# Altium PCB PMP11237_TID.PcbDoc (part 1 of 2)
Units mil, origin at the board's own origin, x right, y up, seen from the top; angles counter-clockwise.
Board outline 9200 x 5000 mil, 2 copper layers (Top Layer, Bottom Layer), stack 62 mil thick; 181 components, 96 nets, 449 pads, 4 vias.
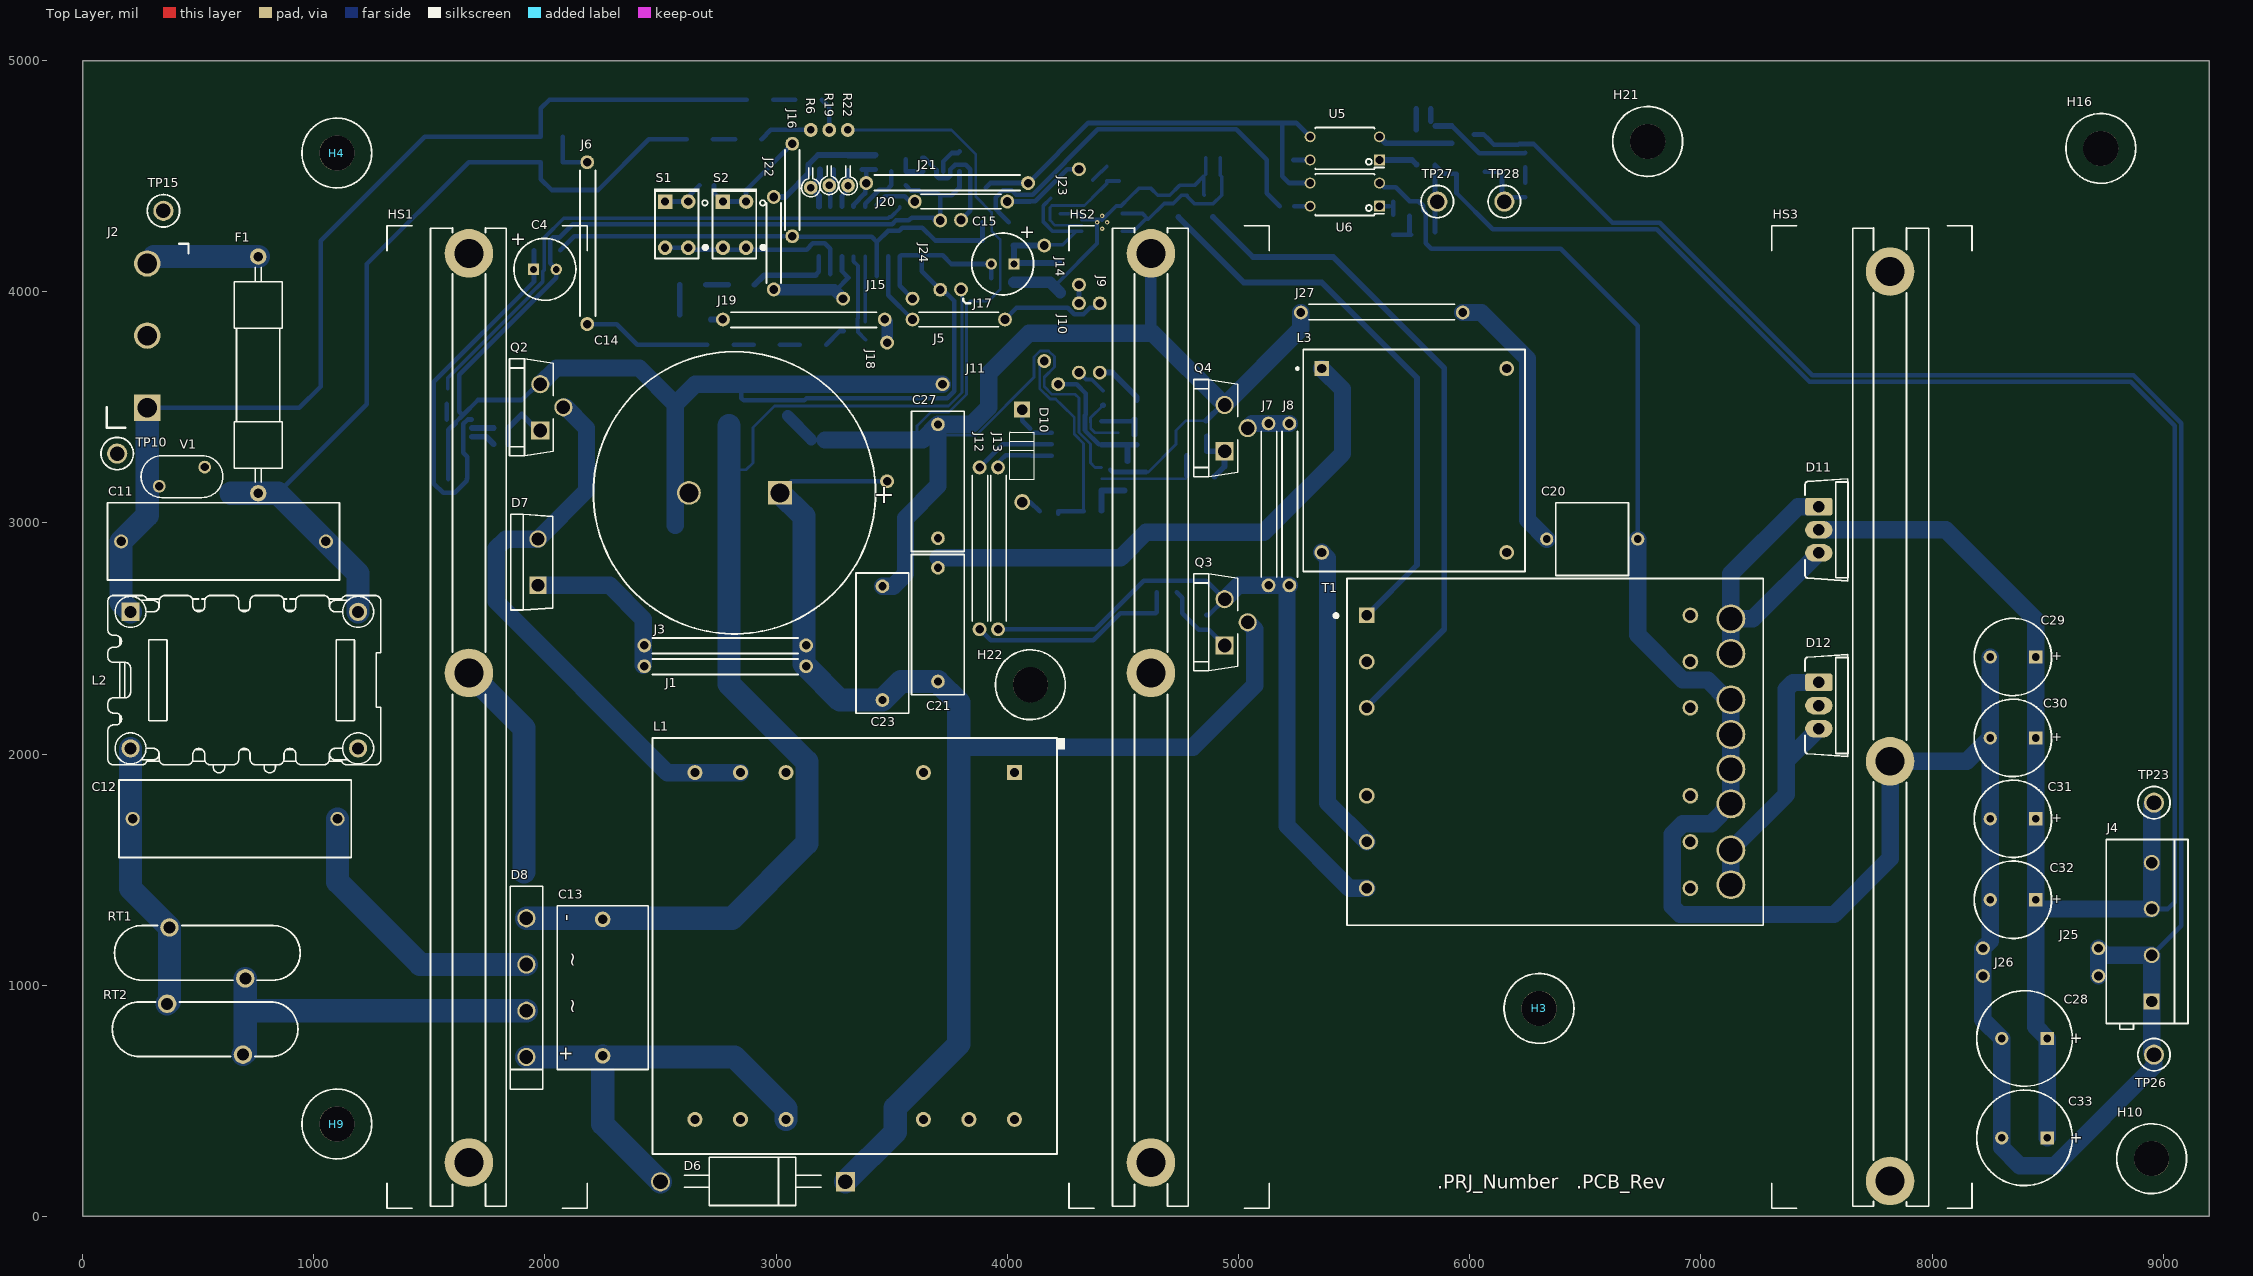
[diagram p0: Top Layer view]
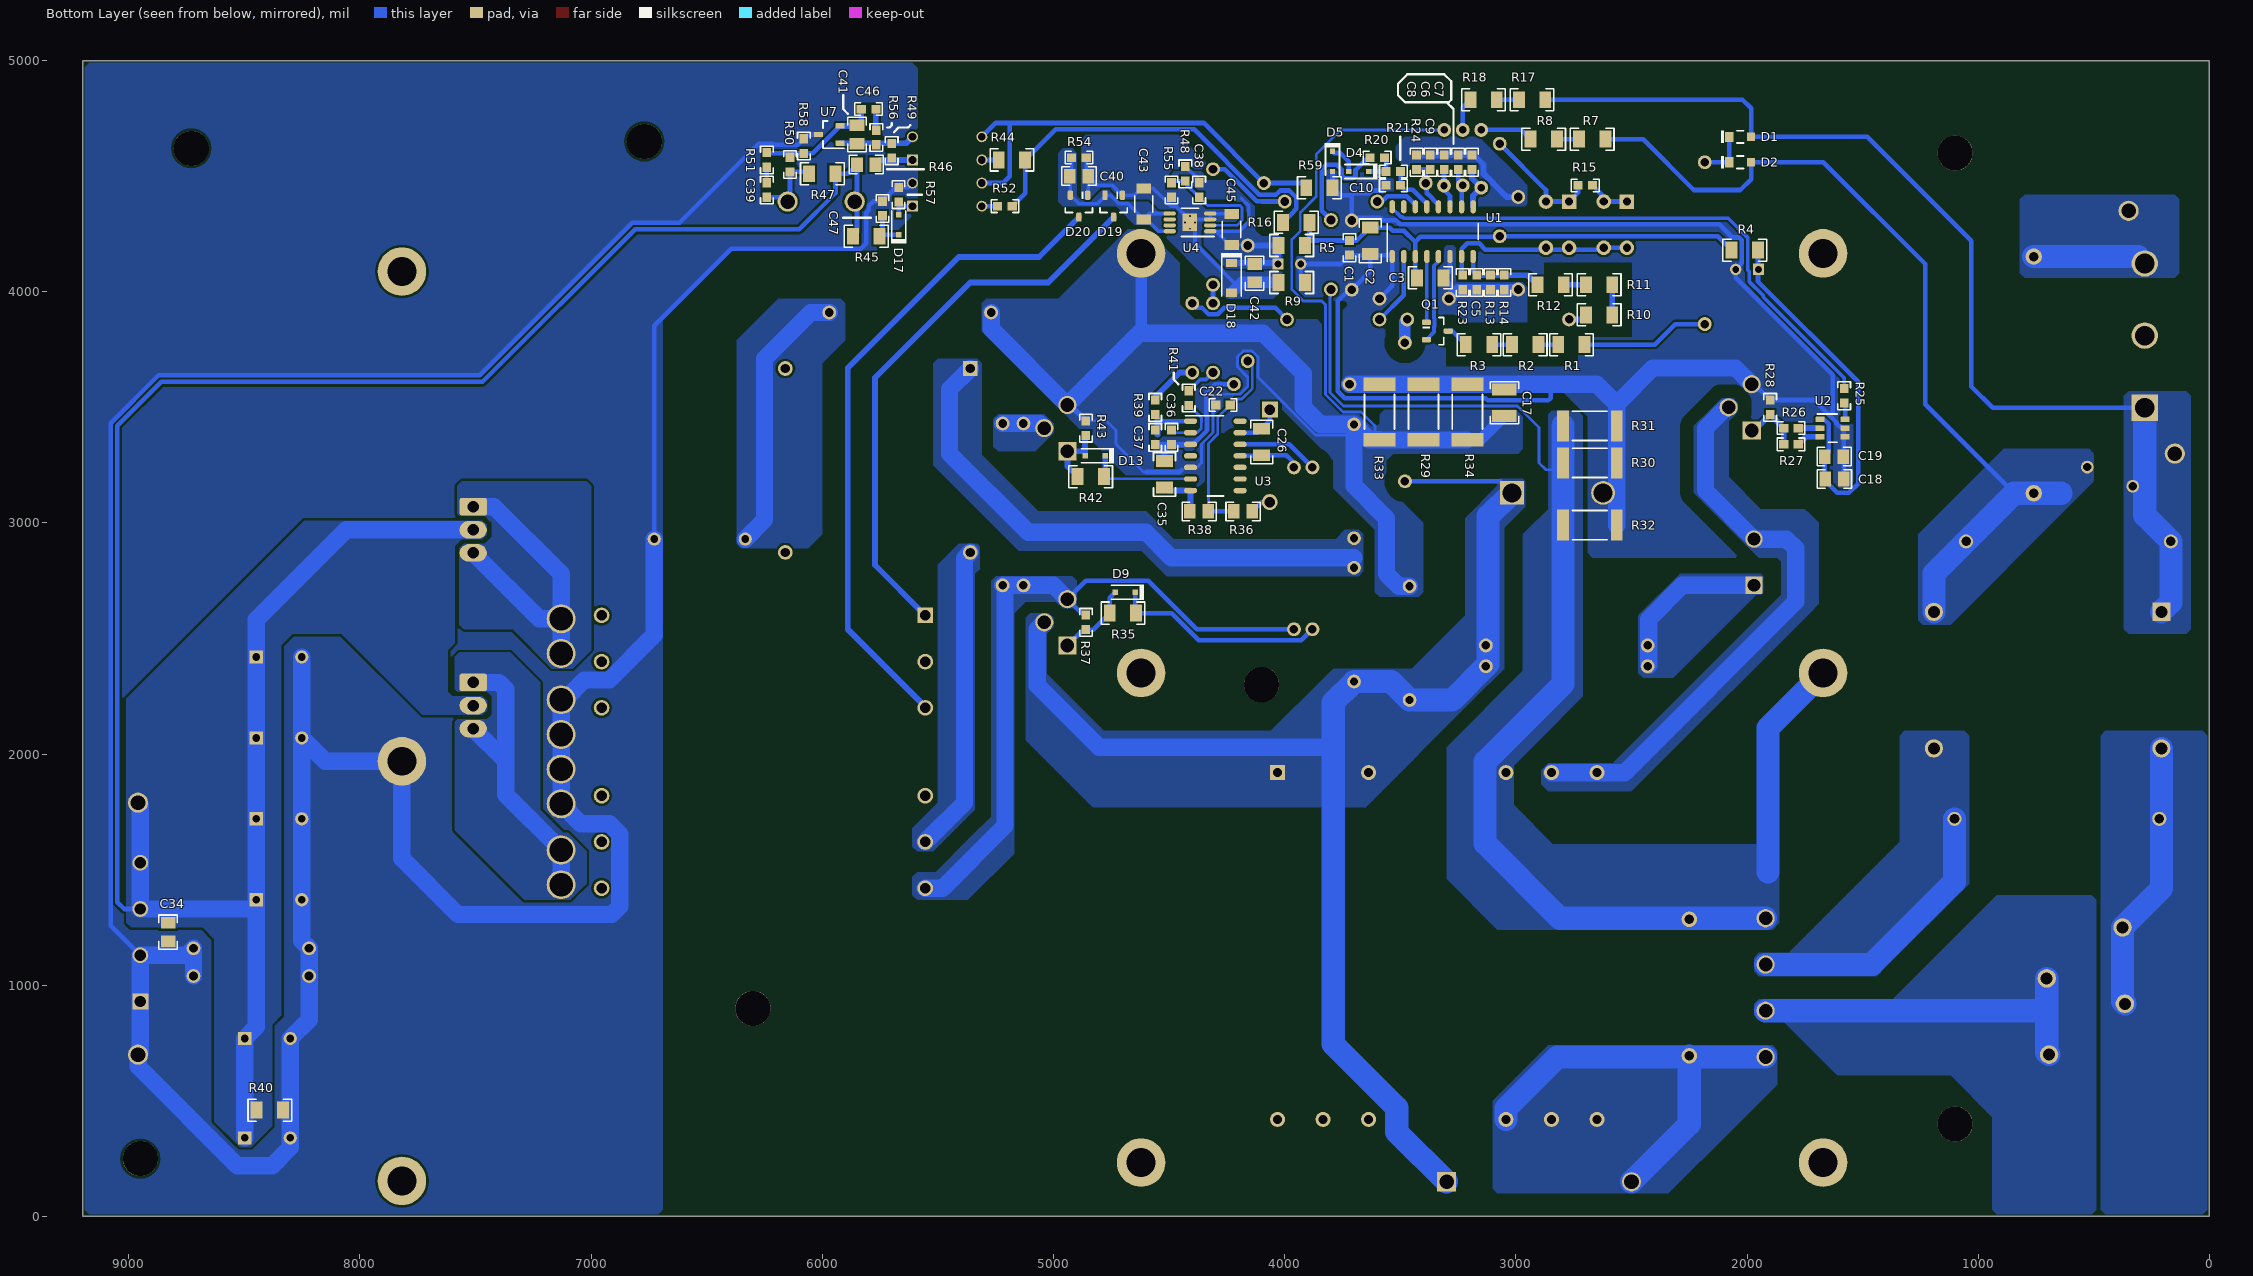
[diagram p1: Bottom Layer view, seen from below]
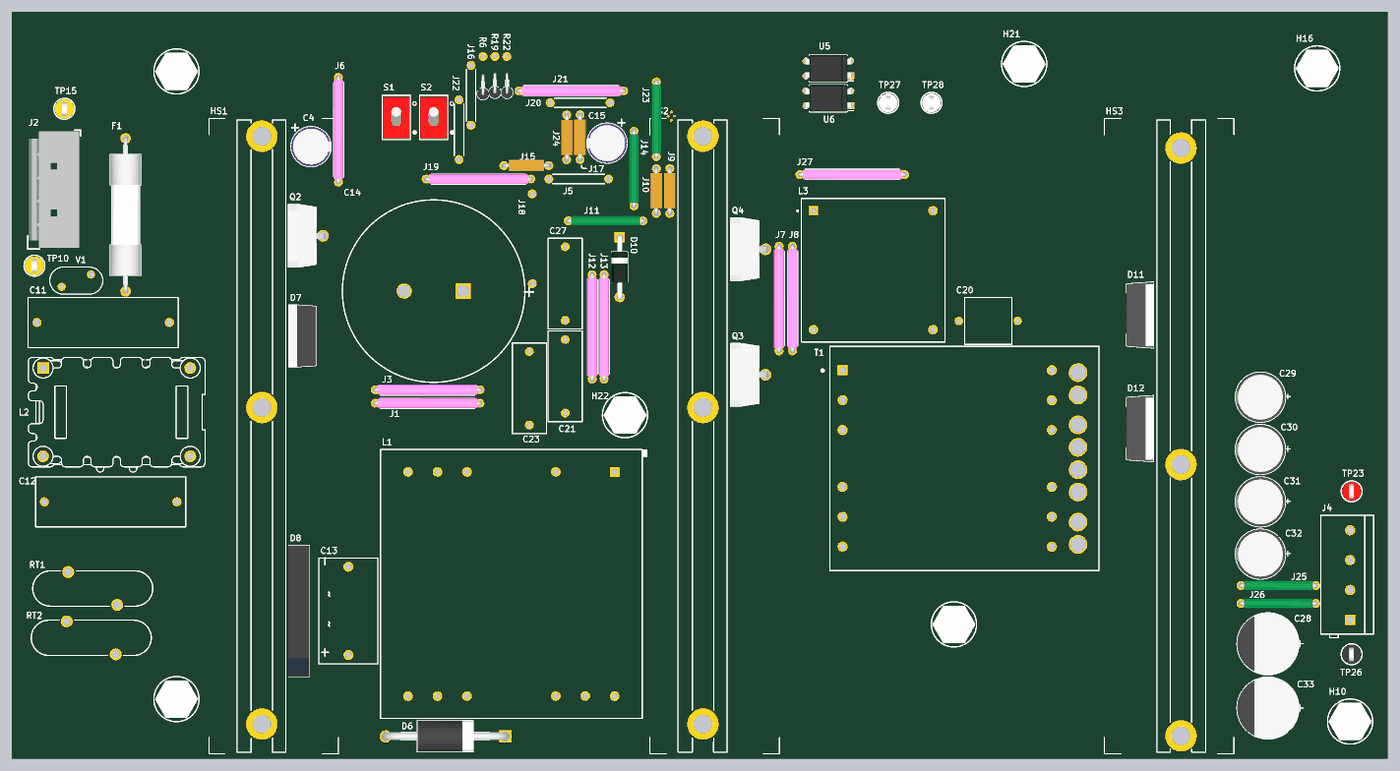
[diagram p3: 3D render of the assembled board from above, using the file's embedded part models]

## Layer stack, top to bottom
Top Solder: solder mask 0.4, Solder Resist, Dk 3.5
Top Layer: signal copper 1.4
Dielectric1: core 59.2, FR-4, Dk 4.8
Bottom Layer: signal copper 1.4
Bottom Solder: solder mask 0.4, Solder Resist, Dk 3.5

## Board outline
0,0 9200,0 9200,5000 0,5000

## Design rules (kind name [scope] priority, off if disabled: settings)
AcuteAngle [All] p1: minimum=4.50000000000000E+0001 checktracksonly=FALSE
AssemblyTestPointUsage [All] p1: valid=2
Clearance Clearance_1 [InNetClass('HV') vs (InNet('AGND') OR InNet('PGND') OR InNet('SEC_0V') OR InNet('PFCCS') OR InNet('LLC_RCS'))] p1: gap=60
Clearance Clearance_Keepouts [((IsTrack Or IsArc) And Not InPoly) And IsFree and IsKeepOut vs ((IsTrack Or IsArc) And Not InPoly) And IsFree and IsKeepOut] p2: gap=0
Clearance Clearance_BoardEdge_MountingHoles [OnCopper and InComponentClass('Mounting Holes') vs IsKeepOut] p3: gap=40
Clearance Clearance_BoardEdge_Poly [OnCopper and InPoly vs IsKeepOut] p4: gap=25
Clearance Clearance_BoardEdge [OnCopper and Not InComponentClass('Logo') and not InComponentClass('FiducialMark') and not InRegion(1000,500,4000,800) and Not IsKeepout vs IsKeepOut] p5: gap=75
Clearance Clearance_Poly [InPolygon] p6: gap=10
Clearance [All] p7: gap=7.87
ComponentClearance ComponentClearance_MountingHoles_FiducialMarks [InComponentClass('Mounting Holes') vs InComponentClass('FiducialMark')] p1: gap=20 collisioncheckmode=3 verticalgap=10 showdistances=FALSE
ComponentClearance ComponentClearance_Shunt [InComponentClass('Header') vs InComponentClass('Shunt')] p2: gap=0 collisioncheckmode=3 verticalgap=0 showdistances=FALSE
ComponentClearance ComponentClearance_Logo [InComponentClass('Logo')] p3: gap=5 collisioncheckmode=3 verticalgap=10 showdistances=FALSE
ComponentClearance ComponentClearance_ScrewToNut [(HasFootprint('NY PMS 440 0025 PH')) vs (HasFootprint('Keystone_1902C'))] p4: gap=20 collisioncheckmode=3 verticalgap=100000 showdistances=FALSE
ComponentClearance ComponentClearance_MountingHoles [InComponentClass('Mounting Holes')] p5: gap=20 collisioncheckmode=3 verticalgap=10 showdistances=FALSE
ComponentClearance ComponentClearance_SmallPassives [HasFootprint('0201*') or HasFootprint('0402*') or HasFootprint('0508') or HasFootprint('0603*') or HasFootprint('0612') or HasFootprint('0805*') or HasFootprint('0815*') or HasFootprint('0830*') or HasFootprint('1206*') or HasFootprint('1210*') or HasFootprint('1808*') or HasFootprint('1812*') or HasFootprint('1825*') or HasFootprint('2010*') or HasFootprint('2220*') or HasFootprint('2225*') or HasFootprint('2512*') or HasFootprint('2728*') or HasFootprint('3518*') vs HasFootprint('0201*') or HasFootprint('0402*') or HasFootprint('0508') or HasFootprint('0603*') or HasFootprint('0612') or HasFootprint('0805*') or HasFootprint('0815*') or HasFootprint('0830*') or HasFootprint('1206*') or HasFootprint('1210*') or HasFootprint('1808*') or HasFootprint('1812*') or HasFootprint('1825*') or HasFootprint('2010*') or HasFootprint('2220*') or HasFootprint('2225*') or HasFootprint('2512*') or HasFootprint('2728*') or HasFootprint('3518*')] p6: gap=20 collisioncheckmode=3 verticalgap=20 showdistances=FALSE
ComponentClearance ComponentClearance_THtoSMT [IsThruComponent vs IsSMTComponent] p7: gap=10 collisioncheckmode=3 verticalgap=10 showdistances=FALSE
ComponentClearance ComponentClearance_THtoTH [IsThruComponent vs IsThruComponent] p8: gap=6 collisioncheckmode=3 verticalgap=6 showdistances=FALSE
ComponentClearance [All] p9: gap=10 collisioncheckmode=3 verticalgap=10 showdistances=FALSE
DiffPairsRouting [All] p1: maxlimit=100 minlimit=10 mostfreqgap=10 toplayer_minwidth=15 toplayer_maxwidth=15 toplayer_prefwidth=15 bottomlayer_minwidth=15 bottomlayer_maxwidth=15 bottomlayer_prefwidth=15 maxuncoupledlength=1000
FabricationTestPointUsage TestPointUsage [All] p1: valid=2 allowmultiple=FALSE
FabricationTestpoint Testpoint [All] p1: side=3 testpointundercomponent=TRUE minsize=40 maxsize=100 preferedsize=60 minholesize=0 maxholesize=40 preferedholesize=32 testpointgrid=1 allowsidetop=TRUE allowsidebottom=TRUE usegrid=TRUE gridtolerance=0.01
FanoutControl Fanout_LCC [IsLCC] p1: bgadir=Out bgaviamode=Centered fanoutstyle=Auto fanoutdirection=Alternating viagrid=1 // Fanout_LCC (Default Rule)
FanoutControl Fanout_BGA [IsBGA] p2: bgadir=Out bgaviamode=Centered fanoutstyle=Auto fanoutdirection=Alternating viagrid=1 // Fanout_BGA (Default Rule)
FanoutControl Fanout_Default [All] p4: bgadir=Out bgaviamode=Centered fanoutstyle=Auto fanoutdirection=Alternating viagrid=1 // Fanout_Default (Default Rule)
FanoutControl Fanout_Small [(CompPinCount < 5)] p5: bgadir=Out bgaviamode=Centered fanoutstyle=Auto fanoutdirection=OutThenIn viagrid=1 // Fanout_Small (Default Rule)
Height [All] p1: minheight=0 maxheight=3000 prefheight=500
HoleSize [All] p1: absolutevalues=TRUE maxlimit=251 minlimit=7 maxpercent=80.000 minpercent=20.000
MinimumAnnularRing MinimumAnnularRing_ThermalPadVias [IsVia and InAnyComponent] p1: minimumring=5.91
MinimumAnnularRing [All] p2: minimumring=6
MinimumSolderMaskSliver MinimumSolderMaskSliver_Logo [InComponentClass('Logo') vs InComponentClass('Logo')] p1: minsoldermaskwidth=0.7
MinimumSolderMaskSliver [All] p2: minsoldermaskwidth=2
PlaneConnect [All] p1: planeconnectstyle=Relief reliefexpansion=10 reliefentries=4 reliefconductorwidth=10 reliefairgap=10
PolygonConnect PolygonConnect_13 [All vs IsNamedPolygon('C35_2') Or  IsNamedPolygon('L3_6') Or  IsNamedPolygon('PFCCS') Or  IsNamedPolygon('D7_2') Or  IsNamedPolygon('C40_2') Or  IsNamedPolygon('D7_1') Or  IsNamedPolygon('D11_1') Or  IsNamedPolygon('C12_1') Or  IsNamedPolygon('J7_2') Or  IsNamedPolygon('D8_2') Or  IsNamedPolygon('C20_2') Or  IsNamedPolygon('C12_2') Or  IsNamedPolygon('C15_1') Or  IsNamedPolygon('J7_1') Or  IsNamedPolygon('C13_1') Or  IsNamedPolygon('D12_1') Or  IsNamedPolygon('+Vout') Or  IsNamedPolygon('LLC_RCS') Or  IsNamedPolygon('AGND') Or  IsNamedPolygon('PGND') Or  IsNamedPolygon('AGND1') Or  IsNamedPolygon('SGND') Or  IsNamedPolygon('C21_2') Or  IsNamedPolygon('Bulk') Or  IsNamedPolygon('C40_1') Or  IsNamedPolygon('AC2') Or  IsNamedPolygon('AC1') Or  IsNamedPolygon('F1_2')] p1: connectstyle=Direct reliefconductorwidth=10 reliefentries=4 polygonreliefangle="90 Angle" airgapwidth=10
PolygonConnect PolygonConnect_12 [All vs IsNamedPolygon('F1_2') Or  IsNamedPolygon('+Vout') Or  IsNamedPolygon('AC1') Or  IsNamedPolygon('C40_2') Or  IsNamedPolygon('C12_2') Or  IsNamedPolygon('D7_2') Or  IsNamedPolygon('AGND') Or  IsNamedPolygon('PFCCS') Or  IsNamedPolygon('D8_2') Or  IsNamedPolygon('C21_2') Or  IsNamedPolygon('D12_1') Or  IsNamedPolygon('C40_1') Or  IsNamedPolygon('AC2') Or  IsNamedPolygon('C12_1') Or  IsNamedPolygon('PGND') Or  IsNamedPolygon('J7_2') Or  IsNamedPolygon('C15_1') Or  IsNamedPolygon('D11_1') Or  IsNamedPolygon('D7_1') Or  IsNamedPolygon('J7_1') Or  IsNamedPolygon('LLC_RCS') Or  IsNamedPolygon('SGND') Or  IsNamedPolygon('Bulk') Or  IsNamedPolygon('AGND1') Or  IsNamedPolygon('C13_1') Or  IsNamedPolygon('C20_2') Or  IsNamedPolygon('L3_6')] p2: connectstyle=Direct reliefconductorwidth=10 reliefentries=4 polygonreliefangle="90 Angle" airgapwidth=10
PolygonConnect PolygonConnect_11 [All vs IsNamedPolygon('F1_2') Or  IsNamedPolygon('D8_2') Or  IsNamedPolygon('C21_2') Or  IsNamedPolygon('SGND') Or  IsNamedPolygon('LLC_RCS') Or  IsNamedPolygon('D7_1') Or  IsNamedPolygon('D7_2') Or  IsNamedPolygon('C40_2') Or  IsNamedPolygon('AC2') Or  IsNamedPolygon('C40_1') Or  IsNamedPolygon('D11_1') Or  IsNamedPolygon('J7_2') Or  IsNamedPolygon('C13_1') Or  IsNamedPolygon('C12_1') Or  IsNamedPolygon('Bulk') Or  IsNamedPolygon('C12_2') Or  IsNamedPolygon('L3_6') Or  IsNamedPolygon('J7_1') Or  IsNamedPolygon('PGND') Or  IsNamedPolygon('AGND1') Or  IsNamedPolygon('C20_2') Or  IsNamedPolygon('PFCCS') Or  IsNamedPolygon('+Vout') Or  IsNamedPolygon('C15_1') Or  IsNamedPolygon('AC1') Or  IsNamedPolygon('AGND') Or  IsNamedPolygon('D12_1')] p3: connectstyle=Direct reliefconductorwidth=10 reliefentries=4 polygonreliefangle="90 Angle" airgapwidth=10
PolygonConnect PolygonConnect_10 [All vs IsNamedPolygon('C12_2') Or  IsNamedPolygon('AC1') Or  IsNamedPolygon('AC2') Or  IsNamedPolygon('C12_1') Or  IsNamedPolygon('D8_2') Or  IsNamedPolygon('C21_2') Or  IsNamedPolygon('D7_2') Or  IsNamedPolygon('LLC_RCS') Or  IsNamedPolygon('L3_6') Or  IsNamedPolygon('J7_2') Or  IsNamedPolygon('Bulk') Or  IsNamedPolygon('PGND') Or  IsNamedPolygon('J7_1') Or  IsNamedPolygon('PFCCS') Or  IsNamedPolygon('D7_1') Or  IsNamedPolygon('AGND1') Or  IsNamedPolygon('C20_2') Or  IsNamedPolygon('C13_1') Or  IsNamedPolygon('AGND') Or  IsNamedPolygon('F1_2')] p4: connectstyle=Direct reliefconductorwidth=10 reliefentries=4 polygonreliefangle="90 Angle" airgapwidth=10
PolygonConnect PolygonConnect_9 [All vs IsNamedPolygon('F1_2') Or  IsNamedPolygon('Bulk') Or  IsNamedPolygon('C12_1') Or  IsNamedPolygon('C13_1') Or  IsNamedPolygon('AC1') Or  IsNamedPolygon('D8_2') Or  IsNamedPolygon('C12_2') Or  IsNamedPolygon('D7_1') Or  IsNamedPolygon('D7_2') Or  IsNamedPolygon('J7_1') Or  IsNamedPolygon('AC2') Or  IsNamedPolygon('AGND1') Or  IsNamedPolygon('AGND') Or  IsNamedPolygon('L3_6') Or  IsNamedPolygon('C21_2') Or  IsNamedPolygon('LLC_RCS') Or  IsNamedPolygon('J7_2') Or  IsNamedPolygon('PFCCS')] p5: connectstyle=Direct reliefconductorwidth=10 reliefentries=4 polygonreliefangle="90 Angle" airgapwidth=10
PolygonConnect PolygonConnect_8 [All vs IsNamedPolygon('Bulk') Or  IsNamedPolygon('C12_2') Or  IsNamedPolygon('C13_1') Or  IsNamedPolygon('AC1') Or  IsNamedPolygon('C21_2') Or  IsNamedPolygon('AC2') Or  IsNamedPolygon('C12_1') Or  IsNamedPolygon('PFCCS') Or  IsNamedPolygon('D7_2') Or  IsNamedPolygon('D8_2') Or  IsNamedPolygon('J7_1') Or  IsNamedPolygon('L3_6') Or  IsNamedPolygon('D7_1') Or  IsNamedPolygon('F1_2')] p6: connectstyle=Direct reliefconductorwidth=10 reliefentries=4 polygonreliefangle="90 Angle" airgapwidth=10
PolygonConnect PolygonConnect_7 [All vs IsNamedPolygon('Bulk') Or  IsNamedPolygon('C12_2') Or  IsNamedPolygon('C13_1') Or  IsNamedPolygon('AC1') Or  IsNamedPolygon('C21_2') Or  IsNamedPolygon('AC2') Or  IsNamedPolygon('C12_1') Or  IsNamedPolygon('PFCCS') Or  IsNamedPolygon('D7_2') Or  IsNamedPolygon('D8_2') Or  IsNamedPolygon('J7_1') Or  IsNamedPolygon('L3_6') Or  IsNamedPolygon('D7_1') Or  IsNamedPolygon('F1_2') Or  IsNamedPolygon('J7_2') Or  IsNamedPolygon('LLC_RCS')] p7: connectstyle=Direct reliefconductorwidth=10 reliefentries=4 polygonreliefangle="90 Angle" airgapwidth=10
PolygonConnect PolygonConnect_6 [All vs IsNamedPolygon('GND2') Or  IsNamedPolygon('SGND') Or  IsNamedPolygon('GND1') Or  IsNamedPolygon('C901_1') Or  IsNamedPolygon('SGND') Or  IsNamedPolygon('GND2') Or  IsNamedPolygon('GND1')] p8: connectstyle=Direct reliefconductorwidth=10 reliefentries=4 polygonreliefangle="90 Angle" airgapwidth=10
PolygonConnect PolygonConnect_5 [All vs IsNamedPolygon('GND1') Or  IsNamedPolygon('GND1')] p9: connectstyle=Direct reliefconductorwidth=10 reliefentries=4 polygonreliefangle="90 Angle" airgapwidth=10
PolygonConnect PolygonConnect_4 [All vs IsNamedPolygon('C21_1') Or  IsNamedPolygon('C5_1') Or  IsNamedPolygon('C12_2') Or  IsNamedPolygon('C2_2') Or  IsNamedPolygon('C13_1') Or  IsNamedPolygon('C28_1') Or  IsNamedPolygon('C6_1') Or  IsNamedPolygon('GND') Or  IsNamedPolygon('GND2') Or  IsNamedPolygon('C14_1') Or  IsNamedPolygon('C13_1') Or  IsNamedPolygon('Q1_3') Or  IsNamedPolygon('C14_1') Or  IsNamedPolygon('C5_1') Or  IsNamedPolygon('GND2') Or  IsNamedPolygon('C28_1') Or  IsNamedPolygon('D5_2') Or  IsNamedPolygon('D6_2') Or  IsNamedPolygon('D2_1') Or  IsNamedPolygon('C12_2') Or  IsNamedPolygon('D2_1') Or  IsNamedPolygon('C4_1') Or  IsNamedPolygon('C4_1') Or  IsNamedPolygon('C2_2') Or  IsNamedPolygon('GND') Or  IsNamedPolygon('C33_1') Or  IsNamedPolygon('C9_1')] p10: connectstyle=Direct reliefconductorwidth=10 reliefentries=4 polygonreliefangle="90 Angle" airgapwidth=10
PolygonConnect PolygonConnect_3 [All vs IsNamedPolygon('C28_1') Or  IsNamedPolygon('C12_2') Or  IsNamedPolygon('C28_1') Or  IsNamedPolygon('C9_1') Or  IsNamedPolygon('D5_2') Or  IsNamedPolygon('C12_2') Or  IsNamedPolygon('C2_2') Or  IsNamedPolygon('C14_1') Or  IsNamedPolygon('C4_1') Or  IsNamedPolygon('C14_1') Or  IsNamedPolygon('D6_2') Or  IsNamedPolygon('GND2') Or  IsNamedPolygon('Q1_3') Or  IsNamedPolygon('C5_1') Or  IsNamedPolygon('D2_1') Or  IsNamedPolygon('C4_1') Or  IsNamedPolygon('C13_1') Or  IsNamedPolygon('C5_1') Or  IsNamedPolygon('C13_1') Or  IsNamedPolygon('C33_1') Or  IsNamedPolygon('D2_1') Or  IsNamedPolygon('GND') Or  IsNamedPolygon('GND') Or  IsNamedPolygon('GND2') Or  IsNamedPolygon('C2_2') Or  IsNamedPolygon('C6_1') Or  IsNamedPolygon('C21_1')] p11: connectstyle=Direct reliefconductorwidth=10 reliefentries=4 polygonreliefangle="90 Angle" airgapwidth=10
PolygonConnect PolygonConnect_2 [All vs IsNamedPolygon('C21_1') Or  IsNamedPolygon('C4_1') Or  IsNamedPolygon('D5_2') Or  IsNamedPolygon('C5_1') Or  IsNamedPolygon('C14_1') Or  IsNamedPolygon('C13_1') Or  IsNamedPolygon('C4_1') Or  IsNamedPolygon('C33_1') Or  IsNamedPolygon('C12_2') Or  IsNamedPolygon('D2_1') Or  IsNamedPolygon('C2_2') Or  IsNamedPolygon('C28_1') Or  IsNamedPolygon('C12_2') Or  IsNamedPolygon('D2_1') Or  IsNamedPolygon('C5_1') Or  IsNamedPolygon('Q1_3') Or  IsNamedPolygon('GND') Or  IsNamedPolygon('D6_2') Or  IsNamedPolygon('C6_1') Or  IsNamedPolygon('C2_2') Or  IsNamedPolygon('C14_1') Or  IsNamedPolygon('C28_1') Or  IsNamedPolygon('C13_1') Or  IsNamedPolygon('C9_1') Or  IsNamedPolygon('GND')] p12: connectstyle=Direct reliefconductorwidth=10 reliefentries=4 polygonreliefangle="90 Angle" airgapwidth=10
PolygonConnect PolygonConnect_1 [All vs IsNamedPolygon('C28_1') Or  IsNamedPolygon('D5_2') Or  IsNamedPolygon('C5_1') Or  IsNamedPolygon('C5_1') Or  IsNamedPolygon('D2_1') Or  IsNamedPolygon('C21_1') Or  IsNamedPolygon('C9_1') Or  IsNamedPolygon('C4_1') Or  IsNamedPolygon('C14_1') Or  IsNamedPolygon('C28_1') Or  IsNamedPolygon('C6_1') Or  IsNamedPolygon('C12_2') Or  IsNamedPolygon('C33_1') Or  IsNamedPolygon('C4_1') Or  IsNamedPolygon('C13_1') Or  IsNamedPolygon('C12_2') Or  IsNamedPolygon('D6_2') Or  IsNamedPolygon('C2_2') Or  IsNamedPolygon('C14_1') Or  IsNamedPolygon('D2_1') Or  IsNamedPolygon('C2_2') Or  IsNamedPolygon('C13_1')] p13: connectstyle=Direct reliefconductorwidth=10 reliefentries=4 polygonreliefangle="90 Angle" airgapwidth=10
PolygonConnect [All] p14: connectstyle=Relief reliefconductorwidth=10 reliefentries=4 polygonreliefangle="90 Angle" airgapwidth=10
RoutingVias ThermalPadVias [IsVia and InAnyComponent] p1: holewidth=7.87 width=19.68 viastyle="Through Hole" minholewidth=7.87 minwidth=19.68 maxholewidth=12.99 maxwidth=23.62
RoutingVias [All] p2: holewidth=16 width=34 viastyle="Through Hole" minholewidth=7.87 minwidth=26 maxholewidth=40 maxwidth=65
SilkToBoardRegionClearance [Not ((IsComment or IsDesignator) And (Hide <> 'False')) and not InRegion(1000,500,4000,800)] p1:
SilkToSilkClearance SilkToSilkClearance_Pb-FreeLogo [(HasFootprint('Pb-Free_Overlay_Medium') OR HasFootprint('Pb-Free_Overlay_Small')) vs (HasFootprint('Pb-Free_Overlay_Medium') OR HasFootprint('Pb-Free_Overlay_Small'))] p1: silktosilkclearance=0
SilkToSilkClearance [All] p2: silktosilkclearance=1
SilkToSolderMaskClearance "Silk to Solder Mask Opening" [All] p1: minsilkscreentomaskgap=1 clearancetoexposedcopper=FALSE
SolderMaskExpansion [All] p1: expansion=1.97
UnpouredPolygon [All] p1: allowunpoured=FALSE
Width [All] p1: maxlimit=100 minlimit=6 preferedwidth=10 checkconnectedcopper=TRUE
13 further rules are at their usual default settings.

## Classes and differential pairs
component class PMP11237_TID_Hardware: H3 H4 H9 H10 H16 H21 H22 Logo5
component class PMP11237_BlankSheet: C1 C2 C3 C5 C6 C7 C8 C9 C10 D1 D2 D4 D5 J5 J6 J15 J16 J17 J18 J19 J20 J21 J22 J23 J24 Q1 R1 R2 R3 R6 R7 R8 R10 R11 R12 R13 R14 R15 R17 R18 R19 R20 R21 R22 R23 R24 S1 S2 U1
net class HV: AC1 AC2 BULK NetC12_1 NetC12_2 NetC13_1 NetC26_2 NetD1_1 NetD7_1 NetD7_2 NetD8_2 NetD9_1 NetF1_2 NetJ7_1 NetJ7_2 NetJ12_2 NetJ18_1 NetJ19_1 NetL3_6 NetQ1_3 NetR1_2 NetR2_2 NetR7_1 NetR10_2 NetR11_2 NetR17_1

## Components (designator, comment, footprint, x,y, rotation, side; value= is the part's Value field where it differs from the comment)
C1 "06035C104KAT2A" 0603 3720,4190 r270 bottom
C2 "GMK316AB7106KL" 1206 3630,4220 r90 bottom
C3 "GMK316AB7106KL" 1206 3370,4060 r0 bottom
C4 "EEU-EB1E101S" CAPPR250W50D630H1120 2000,4096.79 r0 top
C5 "C0603C471K5RACTU" 0603 3170,4040 r270 bottom
C6 "C0603C471K5RACTU" 0603 3250,4560 r90 bottom
C7 "C0603C471K5RACTU" 0603 3190,4560 r90 bottom
C8 "06035C104KAT2A" 0603 3310,4560 r90 bottom
C9 "06033C104KAT2A" 0603 3370,4560 r90 bottom
C10 "C0603C102K5RACTU" 0603 3530,4460 r180 bottom
C11 "ECQ-U2A474ML" CAPRR2250W80L2550T850H1750 610,2920 r0 top
C12 "ECQ-U2A474ML" CAPRR2250W80L2550T850H1750 660,1720 r0 top
C13 "ECQ-U2A334ML" CAPRR1500W80L1750T950H1750 2250,990 r90 top
C14 "380LQ271M450K022" 380LQ_3000x3000 2820,3130 r180 top
C15 "EEU-EB1E101S" CAPPR250W50D630H1120 3980,4120 r180 top
C17 "GRM32ER70J476KE20L" 1210 3050,3520 r90 bottom
C18 "08055C104JAT2A" 0805_HV 1622.34,3190 r180 bottom
C19 "GRM21BR71H105KA12L" 0805_HV 1623.31,3286.5 r180 bottom
C20 "DE1E3KX102MA5BA01" DE_800x1200x800 6530,2930 r180 top
C21 "ECW-F6163JL" ECWH_8123HA 3700,2560 r90 top
C22 "UMK107AB7105KA-T" 0603 4267,3510 r180 bottom
C23 "ECW-H8123HA" ECWH_8123HA 3460,2480 r90 top
C26 "C3216C0G1E104J" 1206 4100,3350 r270 bottom
C27 "ECW-F6163JL" ECWH_8123HA 3700,3180 r90 top
C28 "APS-160ELL331MJC5S" PS_1000x1250 8400,770 r180 top
C29 "EEU-FR1C102L" FR_800x2000 8350,2420 r180 top
C30 "EEU-FR1C102L" FR_800x2000 8350,2070 r180 top
C31 "EEU-FR1C102L" FR_800x2000 8350,1720 r180 top
C32 "EEU-FR1C102L" FR_800x2000 8350,1370 r180 top
C33 "APS-160ELL331MJC5S" PS_1000x1250 8400,340 r180 top
C34 "GRM21BR71H105KA12L" 0805_HV 8830,1230 r270 bottom
C35 "12063C105KAT2A" 1206 4520,3210 r90 bottom
C36 "06035A101FAT2A" 0603 4490,3370 r270 bottom
C37 "06035A101FAT2A" 0603 4560,3370 r90 bottom
C38 "C0603C103K5RACTU" 0603 4370,4440 r270 bottom
C39 "NF" 0603 6240,4440 r90 bottom
C40 "08055C104JAT2A" 0805_HV 4890,4500 r180 bottom
C41 "08055C473KAT2A" 0805_HV 5850,4680 r270 bottom
C42 "08055C104JAT2A" 0805_HV 4130,4080 r270 bottom
C43 "CGA5L3X5R1H106K160AB" 1206_190 4610,4380 r90 bottom
C45 "CGA5L3X5R1H106K160AB" 1206_190 4230,4270 r90 bottom
C46 "NF" 0603 5800,4790 r180 bottom
C47 "C0603C104K4RACTU" 0603 5740,4360 r90 bottom
D1 "DA2JF8100L" SMini2-F5-B 2030,4670 r180 bottom
D2 "DA2JF8100L" SMini2-F5-B 2030,4560 r180 bottom
D4 "BAS316,115" sod-323 3680,4520 r0 bottom
D5 "BAS316,115" sod-323 3793.31,4563.31 r270 bottom
D6 "1N5406" DO-201AD 2900,150 r180 top
D7 "C3D04060A" TO-220-F2 1970,2830 r90 top
D8 "GBU8J-BP" GBU 1920,990 r90 top
D9 "NF" sod-323 4689.69,2700 r0 bottom
D10 "MUR160-TP" DO-41 4064.57,3290 r270 top
D11 "STPS40L45CT" TO-220AB 7510,2970 r270 top
D12 "STPS40L45CT" TO-220AB 7510,2210 r270 top
D13 "NF" sod-323 4820,3290 r0 bottom
D17 "BZX384-C12,115" sod-323 5670,4290 r90 bottom
D18 "MMSZ5248B-7-F" SOD-123 4230,4060 r270 bottom
D19 "BAV99,215" SOT-23 4740,4370 r270 bottom
D20 "BAV99,215" SOT-23 4890,4370 r270 bottom
F1 "0216008.MXESPP" FUSE_0216 760,3640 r90 top
H3 "4824" KEYSTONE_4824 6300,900 r0 top
H4 "4824" KEYSTONE_4824 1100,4600 r0 top
H9 "4824" KEYSTONE_4824 1100,400 r0 top
H10 "4824" KEYSTONE_4824 8950,250 r0 top
H16 "4824" KEYSTONE_4824 8730,4620 r0 top
H21 "4824" KEYSTONE_4824 6770,4650 r0 top
H22 "4824" KEYSTONE_4824 4100,2300 r0 top
HS1 "782653B04250G" HEATSINK_782653B04250G 1750,2160 r270 top
HS2 "782653B04250G" HEATSINK_782653B04250G 4700,2160 r270 top
HS3 "782653B04250G" HEATSINK_782653B04250G 7740,2160 r90 top
J1 "923345-07-C" CONN_923345-07-C 2780,2380 r0 top
J2 "1-1318301-3" TE_1-1318301-3 280,3810 r90 top
J3 "923345-07-C" CONN_923345-07-C 2780,2470 r0 top
J4 "ED120/4DS" CONN_ED120_4DS 8950,1230 r180 top
J5 "923345-04-C" 3M_923345-04-C 3790,3880 r0 top
J6 "923345-07-C" CONN_923345-07-C 2183,4210 r90 top
J7 "923345-07-C" CONN_923345-07-C 5130,3080 r90 top
J8 "923345-07-C" CONN_923345-07-C 5220,3080 r90 top
J9 "923345-03-C" 923345-03-C 4400,3800 r270 top
J10 "923345-03-C" 923345-03-C 4310,3800 r270 top
J11 "923345-05-C" 923345-05-C 3970,3600 r180 top
J12 "923345-07-C" CONN_923345-07-C 3880,2890 r90 top
J13 "923345-07-C" CONN_923345-07-C 3960,2890 r90 top
J14 "923345-05-C" 923345-05-C 4160,3950 r270 top
J15 "923345-03-C" 923345-03-C 3440,3970 r180 top
J16 "923345-04-C" 3M_923345-04-C 3070,4440 r270 top
J17 "923345-03-C" 923345-03-C 3800,4160 r270 top
J18 "923345-06-C" CONN_923345-06-C 3480,3480 r270 top
J19 "923345-07-C" CONN_923345-07-C 3120,3880 r0 top
J20 "923345-04-C" 3M_923345-04-C 3800,4390 r180 top
J21 "923345-07-C" CONN_923345-07-C 3740,4470 r180 top
J22 "923345-04-C" 3M_923345-04-C 2990,4210 r90 top
J23 "923345-05-C" 923345-05-C 4310,4280 r90 top
J24 "923345-03-C" 923345-03-C 3710,4158.5 r90 top
J25 "923345-05-C" 923345-05-C 8470,1160 r180 top
J26 "923345-05-C" 923345-05-C 8470,1040 r180 top
J27 "923345-07-C" CONN_923345-07-C 5620,3910 r180 top
L1 "RLTI-1108" RLTI-1108 3340,1170 r270 top
L2 "7448258022" WE-CMB_XL 700,2320 r0 top
L3 "75PR8106" Vitec_75P8106 5760,3270 r0 top
Q1 "BSS126 H6906" SOT-23 3340,3830 r180 bottom
Q2 "AOW25S65" TO-262_100mil 1980,3400 r90 top
Q3 "AOW25S65" TO-262_100mil 4940,2470 r90 top
Q4 "AOW25S65" TO-262_100mil 4940,3310 r90 top
R1 "CRCW12060000Z0EA" 1206 2759.75,3771.24 r0 bottom
R2 "CRCW12060000Z0EA" 1206 2959.75,3771.24 r0 bottom
R3 "CRCW12060000Z0EA" 1206 3159.75,3771.24 r0 bottom
R4 "CRCW12060000Z0EA" 1206 2010,4180 r180 bottom
R5 "CRCW12060000Z0EA" 1206 3970,4200 r180 bottom
R6 "CMF503M0900FLEK" CMF50_Vertical#1 3150,4450 r90 top
R7 "CRCW12063M09FKEA" 1206 2670,4660 r180 bottom
R8 "CRCW12063M09FKEA" 1206 2880,4660 r180 bottom
R9 "CRCW12060000Z0EA" 1206 3970,4040 r180 bottom
R10 "CRCW120610M0FKEA" 1206 2640,3900 r180 bottom
R11 "CRCW120610M0FKEA" 1206 2640,4030 r0 bottom
R12 "CRCW120610M0FKEA" 1206 2850,4030 r0 bottom
R13 "CRCW060375K0FKEA" 0603 3110,4040 r270 bottom
R14 "CRCW06033M30JNEA" 0603 3050,4040 r90 bottom
R15 "CRCW0603100KFKEA" 0603 2700,4460 r0 bottom
R16 "CRCW12060000Z0EA" 1206 3950,4300 r0 bottom
R17 "CRCW12063M09FKEA" 1206 2930,4830 r180 bottom
R18 "CRCW12063M09FKEA" 1206 3140,4830 r180 bottom
R19 "CMF503M0900FLEK" CMF50_Vertical#2 3230,4460 r90 top
R20 "RC0603FR-07470RL" 0603 3600,4580 r180 bottom
R21 "RC0603FR-07470RL" 0603 3530,4520 r180 bottom
R22 "CMF502K2100FHEB" CMF50_Vertical#3 3310.99,4459.02 r90 top
R23 "CRCW0603100KFKEA" 0603 3230,4040 r90 bottom
R24 "CRCW06033K32FKEA" 0603 3430,4560 r90 bottom
R25 "CRCW060310R0JNEA" 0603 1580,3550 r90 bottom
R26 "CRCW06033R30JNEA" 0603 1810,3410 r0 bottom
R27 "CRCW06031R00FKEA" 0603 1810,3340 r0 bottom
R28 "CRCW060310K0FKEA" 0603 1900,3500 r90 bottom
R29 "ERJ-1TRQF1R2U" 2512M 3400,3480 r90 bottom
R30 "CSRN2512FTR100" 2512 2680,3260 r0 bottom
R31 "CSRN2512FTR100" 2512 2680,3420 r0 bottom
R32 "CSRN2512FTR100" 2512 2680,2990 r0 bottom
R33 "ERJ-1TRQF1R2U" 2512M 3590,3480 r90 bottom
R34 "ERJ-1TRQF1R2U" 2512M 3210,3480 r90 bottom
R35 "ERJ-8RQF3R3V" 1206 4699.69,2610 r0 bottom
R36 "CRCW08052R20JNEA" 0805_HV 4180,3050 r180 bottom
R37 "CRCW060310K0FKEA" 0603 4860,2570 r270 bottom
R38 "ERJ-6RQF1R0V" 0805_HV 4370,3050 r180 bottom
R39 "CRCW060351R1FKEA" 0603 4560,3500 r90 bottom
R40 "NF" 1206 8390,460 r0 bottom
R41 "CRCW060351R1FKEA" 0603 4415,3540 r90 bottom
R42 "ERJ-8RQF3R3V" 1206 4839.4,3200.37 r0 bottom
R43 "CRCW060310K0FKEA" 0603 4860,3410 r90 bottom
R44 "RC1206FR-071K2L" 1206 5180,4570 r180 bottom
R45 "CRCW1206100RFKEA" 1206 5810,4240 r0 bottom
R46 "RR1220P-512-D" 0805_HV 5810,4550 r0 bottom
R47 "ERJ-8ENF49R9V" 1206 6000,4510 r180 bottom
R48 "RC0603FR-0710ML" 0603 4430,4510 r90 bottom
R49 "CRCW060310K0FKEA" 0603 5700,4610 r270 bottom
R50 "RC0603FR-0718KL" 0603 6140,4550 r270 bottom
R51 "NF" 0603 6240,4570 r90 bottom
R52 "NF" 0603 5210,4370 r0 bottom
R54 "CRCW0603100KFKEA" 0603 4890,4580 r0 bottom
R55 "CRCW06031M10FKEA" 0603 4490,4440 r270 bottom
R56 "NF" 0603 5766.37,4666.99 r90 bottom
R57 "CRCW06030000Z0EA" 0603 5670,4420 r270 bottom
R58 "CRCW06034K75FKEA" 0603 6080,4630 r270 bottom
R59 "CRCW12061K00FKEA" 1206 3850,4450 r0 bottom
RT1 "CL-60" Thermistor_CL-40 540,1140 r0 top
RT2 "CL-60" Thermistor_CL-40 530,810 r0 top
S1 "200USP9T1A1M2RE" 200USP9xxxxM2 2570,4290 r0 top
S2 "200USP9T1A1M2RE" 200USP9xxxxM2 2820,4290 r0 top
T1 "RLTI-1115" Renco_RLTI-1115 6370,2010 r0 top
TP10 "5014" Keystone5014 150,3300 r0 top
TP15 "5014" Keystone5014 350,4350 r0 top
TP23 "5010" Keystone5010 8960,1790 r0 top
TP26 "5011" Keystone5011 8960,700 r0 top
TP27 "5012" Keystone5012 5860,4390 r0 top
TP28 "5012" Keystone5012 6150,4390 r0 top
U1 "UCC29950DR" D0016A_N 3360,4260 r90 bottom
U2 "UCC27511DBVR" DBV0006A_N 1630,3410 r180 bottom
U3 "UCC27714D" D0014A_N 4300,3290 r180 bottom
U4 "TPS7A1601DGNT" DGN0008C_N 4410,4300 r0 bottom
U5 "PC817X4NSZ0F" DIP762W60P254L460H350Q4B 5460,4620 r180 top
U6 "PC817X4NSZ0F" DIP762W60P254L460H350Q4B 5460,4420 r180 top
U7 "TL431AIDBZR" DBZ0003A_N 5970,4680 r0 bottom
V1 "B72207S2301K101" VAR_S07K300E2 430,3200 r180 top

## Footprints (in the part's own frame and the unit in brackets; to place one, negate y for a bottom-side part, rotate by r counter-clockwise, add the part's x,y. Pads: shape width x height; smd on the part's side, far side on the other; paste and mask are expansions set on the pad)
3M_923345-04-C [mil] "Jumper Wire, 400 mil Spacing, Yellow, Pkg of 200"
  round 60 hole 38: 1(-200,0) 2(200,0)
  silkscreen extent -173,-31 173,31, body extent -215,-30 215,30, height 80
200USP9xxxxM2 [mm] "E-SWITCH"
  rect 1.6x1.6 hole 0.889: 1(-1.27,2.54)
  round 1.6 hole 0.889: 3(-1.27,-2.54) 4(1.27,2.54) 6(1.27,-2.54)
  silkscreen extent -2.5,-3.7 3.4,4, body extent -2.25,-3.5 2.25,3.5, height 11.12
380LQ_3000x3000 [mm] "TH, 2-Leads, Dia 30mm, Pin Spacing 10mm"
  rect 2.6x2.6 hole 2.1: 1(-5,0)
  round 2.6 hole 2.1: 2(5,0)
  silkscreen extent -15.5,-15.5 15.5,15.5, body extent -15.51,-15.51 15.51,15.51, height 32
0603 [mm] "0603 from SM-752 data"
  rect 1x0.95 smd: 1(-0.8,0) 2(0.8,0)
  silkscreen extent -1.52,-0.69 1.52,0.69, body extent -0.87,-0.47 0.87,0.47, height 0.85
0805_HV [mil] "0805 with 30mil clearance between pads"
  rect 50x63 smd: 1(-40,0) 2(40,0)
  silkscreen extent -74,-40 74,40, body extent -43,-29 43,29, height 57
1206 [mm] "1206 from SM-752 data"
  rect 1.3x1.85 smd: 1(-1.45,0) 2(1.45,0)
  silkscreen extent -2.4,-1.21 2.4,1.21, body extent -1.7,-0.9 1.7,0.9, height 1.35
1206_190 [mm] "1206_190"
  rect 1.1x1.6 smd: 1(-1.7,0) 2(1.7,0)
  silkscreen extent -0.9,-1 0.9,1, body extent -1.75,-0.95 1.75,0.95, height 1.9
1210 [mm] "1210 from SM-752 data"
  rect 1.3x2.7 smd: 1(-1.45,0) 2(1.45,0)
  silkscreen extent -2.32,-1.57 2.32,1.57, body extent -1.7,-1.35 1.7,1.35, height 1.35
2512 [mm] "Chip Resistor, Body 6.3x3.2mm, IPC Medium Density"
  rect 1.3x3.4 smd: 1(-2.95,0) 2(2.95,0)
  silkscreen extent -1.9,-1.6 1.9,1.6, body extent -3.22,-1.67 3.22,1.67, height 0.71
2512M [mm] "Chip Resistor, Body 6.3x3.2mm, IPC Low Density"
  rect 1.5x3.5 smd: 1(-3.05,0) 2(3.05,0)
  silkscreen extent -1.9,-1.65 1.9,1.65, body extent -3.22,-1.67 3.22,1.67, height 0.71
923345-03-C [mil] "Wire Jumper"
  round 60 hole 38: 1(-150,0) 2(150,0)
  body extent -163,-40 163,37, height 100
923345-05-C [mil] "Wire Jumper 500mil"
  round 60 hole 38: 1(-250,0) 2(250,0)
  body extent -263,-33 263,33, height 71
CAPPR250W50D630H1120 [mm] "PANASONIC"
  rect 1.25x1.25 hole 0.75: 1(-1.25,0)
  round 1.25 hole 0.75: 2(1.25,0)
  silkscreen extent -3.4,-3.4 3.4,3.4, body extent -3.37,-3.39 3.4,3.39, height 12.21
CAPRR1500W80L1750T950H1750 [mm] "PANASONIC"
  round 1.7 hole 1.069: 1(-7.5,0) 2(7.5,0)
  silkscreen extent -9,-5 9,5, body extent -9,-5 9,5, height 18
CAPRR2250W80L2550T850H1750 [mm] "PANASONIC"
  round 1.55 hole 1.05: 1(-11.25,0) 2(11.25,0)
  silkscreen extent -12.75,-4.25 12.75,4.25, body extent -12.75,-4.25 12.75,4.25, height 17.5
CMF50_Vertical#1 [mil] "Vishay 1/4W resistor"
  round 60 hole 32: 1(0,0) 2(250,0)
  silkscreen extent -40,-40 85,40, body extent -40,-40 134,40, height 299
CMF50_Vertical#2 [mil] "Vishay 1/4W resistor"
  round 60 hole 32: 1(0,0) 2(240,0)
  silkscreen extent -40,-40 85,40, body extent -40,-40 134,40, height 299
CMF50_Vertical#3 [mil] "Vishay 1/4W resistor"
  round 60 hole 32: 1(0,0) 2(240.98,0.99)
  silkscreen extent -40,-40 85,40, body extent -40,-40 134,40, height 299
CONN_923345-06-C [mil] "3M, Wire jumper, 600 mil lenght, Blue"
  round 60 hole 37: 1(-300,0) 2(300,0)
  body extent -313,-35 314,35, height 70
CONN_923345-07-C [mil] "3M, Wire jumper, 700 mil lenght, Violet"
  round 60 hole 37: 1(-350,0) 2(350,0)
  silkscreen extent -315,-35 315,31, body extent -363,-33 363,33, height 74
CONN_ED120_4DS [mm] "ONSHORE"
  rect 1.75x1.75 hole 1.25: 1(0,7.62)
  round 1.75 hole 1.25: 2(0,2.54) 3(0,-2.54) 4(0,-7.62)
  silkscreen extent -4,-10.16 5,10.68, body extent -4.13,-10.01 5.05,10.68, height 13.1
D0014A_N [mm] "SOIC, 14-Leads, Body 8.7x3.9mm, Pitch 1.27mm, IPC Medium Density"
  oval 1.45x0.6 smd: 1(-2.725,3.81) 2(-2.725,2.54) 3(-2.725,1.27) 4(-2.725,0) 5(-2.725,-1.27) 6(-2.725,-2.54) 7(-2.725,-3.81) 8(2.725,-3.81) 9(2.725,-2.54) 10(2.725,-1.27) 11(2.725,0) 12(2.725,1.27) 13(2.725,2.54) 14(2.725,3.81)
  silkscreen extent -3.3,-4.4 0.9,4.4, body extent -3.02,-4.32 3.02,4.32, height 1.6
D0016A_N [mm] "SOIC, 16-Leads, Body 9.9x3.9mm, Pitch 1.27mm, IPC Medium Density"
  oval 1.45x0.6 smd: 1(-2.725,4.445) 2(-2.725,3.175) 3(-2.725,1.905) 4(-2.725,0.635) 5(-2.725,-0.635) 6(-2.725,-1.905) 7(-2.725,-3.175) 8(-2.725,-4.445) 9(2.725,-4.445) 10(2.725,-3.175) 11(2.725,-1.905) 12(2.725,-0.635) 13(2.725,0.635) 14(2.725,1.905) 15(2.725,3.175) 16(2.725,4.445)
  silkscreen extent -3.3,-5 0.9,5, body extent -3,-4.95 3,4.95, height 1.6
DBV0006A_N [mm] "SOT23, 6-Leads, Body 2.9x1.6mm, Pitch 0.95mm, Lead Span 2.8mm, IPC Medium Density"
  rrect17% 1x0.6 smd: 1(-1.375,0.95) 2(-1.375,0) 3(-1.375,-0.95) 4(1.375,-0.95) 5(1.375,0) 6(1.375,0.95)
  silkscreen extent -1.68,-1.55 0.5,1.55, body extent -1.42,-1.46 1.42,1.46, height 1.12
DBZ0003A_N [mm] "SOT23, 3-Leads, Body 2.9x1.3mm, Pitch 0.95mm, Lead Span 2.4mm, IPC Medium Density"
  rrect17% 1x0.6 smd: 1(-1.2,0.95) 2(-1.2,-0.95) 3(1.2,0)
  silkscreen extent -1.65,-1.5 0.7,1.5, body extent -1.26,-1.46 1.26,1.46, height 0.98
DE_800x1200x800 [mm] "Murata"
  round 1.45 hole 0.85 paste+0 mask+0.05: 1(-5,0) 2(5,0)
  silkscreen extent -4,-4 4,4, body extent -5.3,-4 5.3,4, height 11.99
DGN0008C_N [mm] "TSOP, 8-Leads, Body 3x3mm, Pitch 0.65mm, Thermal Pad 1.98x1.88mm, IPC Medium Density"
  rrect100% 1.35x0.45 smd: 1(-2.225,0.975) 2(-2.225,0.325) 3(-2.225,-0.325) 4(-2.225,-0.975) 5(2.225,-0.975) 6(2.225,-0.325) 7(2.225,0.325) 8(2.225,0.975)
  rrect6% 1.6x1.92 smd: 9(0,0)
  silkscreen extent -2.65,-1.55 0.95,1.55, body extent -2.46,-1.5 2.46,1.5, height 1.1
DIP762W60P254L460H350Q4B [mm] "LITE-ON"
  rrect8% 1.2x1.2 hole 0.85: 1(-3.81,1.27)
  round 1.2 hole 0.85: 2(-3.81,-1.27) 3(3.81,-1.27) 4(3.81,1.27)
  silkscreen extent -4.29,-2.29 3.25,2.3, body extent -3.94,-2.3 3.94,2.3, height 4.3
DO-41 [mm] "diode"
  rect 1.75x1.75 hole 1.15: 1(-5.08,0)
  round 1.75 hole 1.15: 2(5.08,0)
  silkscreen extent -2.62,-1.37 2.59,1.35, body extent -5.51,-1.36 5.51,1.36, height 2.72
DO-201AD [mm] "Vishay dimensions"
  rect 2.1x2.1 hole 1.6: 1(-10.16,0)
  round 2.1 hole 1.6: 2(10.16,0)
  silkscreen extent -7.47,-2.7 7.57,2.61, body extent -10.82,-2.74 10.82,2.61, height 5.33
ECWH_8123HA [mm] "Panasonic"
  round 1.5 hole 0.9: 1(-6.25,0) 2(6.25,0)
  silkscreen extent -7.7,-2.9 7.7,2.9, body extent -7.7,-2.9 7.7,2.9, height 11.7
FR_800x2000 [mm] "PANASONIC"
  rect 1.45x1.45 hole 0.85: 1(-2.5,0)
  round 1.45 hole 0.85: 2(2.5,0)
  silkscreen extent -4.25,-4.25 4.25,4.25, body extent -4.22,-4.24 4.24,4.24, height 22.01
FUSE_0216 [mm] "LITTELFUSE"
  round 1.8 hole 1.041: 1(-13,0) 2(13,0)
  silkscreen extent -11.8,-2.65 11.8,2.65, body extent -13.32,-2.65 13.32,2.65, height 5.3
GBU [mm] "Comchip / Diodes Inc diode bridge"
  round 2 hole 1.5: 1(-7.62,0) 2(-2.54,0) 3(2.54,0) 4(7.62,0)
  silkscreen extent -11.15,-1.78 11.15,1.78, body extent -11.15,-1.76 11.15,1.8, height 21.55
HEATSINK_782653B04250G [mil] "Aavid"
  round 210 hole 125: 1(-2006.1,-78.66) 2(-191.14,-78.66) 3(1926.97,-78.66)
  silkscreen extent -2125,-433 2125,433, body extent -2125,-430 2120,420, height 1122
Keystone5010 [mil] "Keystone Multipurpose loops"
  round 87 hole 63: 1(0,0)
  silkscreen extent -70,-70 70,70, body extent -63,-63 63,62, height 319
Keystone5011 [mil] "Keystone Multipurpose loops"
  round 87 hole 63: 1(0,0)
  silkscreen extent -70,-70 70,70, body extent -63,-63 63,62, height 319
Keystone5012 [mil] "Keystone Multipurpose loops"
  round 87 hole 63: 1(0,0)
  silkscreen extent -70,-70 70,70, body extent -63,-63 63,62, height 319
Keystone5014 [mil] "Keystone Multipurpose loops"
  round 87 hole 63: 1(0,0)
  silkscreen extent -70,-70 70,70, body extent -63,-63 63,62, height 319
KEYSTONE_4824 [mil] "HEX STANDOFF 6-32 NYLON 1-1/2\""
  round 1 on Mech3: 0(0,0)
  round 152 hole 152 unplated: MH(0,0)
  silkscreen extent -151,-151 151,151, body extent -144,-125 144,125, height 1500
PS_1000x1250 [mm] "United Chemi-Con"
  rect 1.45x1.45 hole 0.85: 1(-2.5,0)
  round 1.45 hole 0.85: 2(2.5,0)
  silkscreen extent -5.25,-5.25 5.25,5.25, body extent -5.25,-5.24 5.25,5.24, height 14.01
Renco_RLTI-1115 [mil] "Renco"
  rect 68x68 hole 45.3: 1(-815,590)
  round 68 hole 45.3: 2(-815,390) 3(-815,190) 4(-815,-190) 5(-815,-390) 6(-815,-590) 7(585,-590) 8(585,-390) 9(585,-190) 10(585,190) 11(585,390) 12(585,590)
  round 125 hole 102.4: 13(760,575) 14(760,425) 15(760,225) 16(760,75) 17(760,-75) 18(760,-225) 19(760,-425) 20(760,-575)
  silkscreen extent -953,-750 900,750, body extent -900,-750 900,750, height 1550
RLTI-1108 [mm] "RENCO"
  rect 1.65x1.65 hole 1: 1(-19.05,17.551)
  round 1.65 hole 1: 3(-19.05,7.544) 4(-19.05,-7.544) 5(-19.05,-12.548) 6(-19.05,-17.551) 7(19.05,-17.551) 8(19.05,-12.548) 9(19.05,-7.544) 10(19.05,7.544) 11(19.05,12.548) 12(19.05,17.551)
  silkscreen extent -22.86,-22.23 22.86,23.11, body extent -22.86,-22.22 22.86,22.22, height 44.25
SMini2-F5-B [mm] "Panasonic"
  rect 0.9x1.1 smd: 1(-1.2,0)
  rect 0.9x0.9 smd: 2(1.2,0)
  silkscreen extent -2.1,-0.67 0.38,0.67, body extent -0.9,-0.67 0.9,0.67, height 0.81
SOD-123 [mm] "On Semi recommended land pattern"
  rect 0.915x1.22 smd: 1(-1.637,0) 2(1.637,0)
  silkscreen extent -2.74,-1.17 2.03,1.17, body extent -1.93,-0.9 1.93,0.9, height 1.35
sod-323 [mm] "NXP recommended land pattern"
  rect 0.6x0.6 smd paste-0.05: 1(-1.1,0) 2(1.1,0)
  silkscreen extent -2.06,-0.86 1.53,0.86, body extent -1.3,-0.67 1.3,0.68, height 1.1
SOT-23 [mm] "SOT23, 3-Leads, Body 2.9x1.3mm, Pitch 0.95mm, Lead Span 2.5mm, IPC Medium Density"
  rrect50% 1x0.6 smd: 1(-1.2,0.95) 2(-1.2,-0.95) 3(1.2,0)
  silkscreen extent -1.63,-1.5 0.7,1.5, body extent -1.16,-1.45 1.21,1.45, height 1
TE_1-1318301-3 [mm] "TE"
  rect 2.9x2.9 hole 2.15: 1(-7.925,0)
  round 2.9 hole 2.15: 2(0,0) 3(7.925,0)
  silkscreen extent -10.13,-4.53 10.08,4.46, body extent -9.87,-4.28 9.87,4.22, height 10.72
Thermistor_CL-40 [mil] "GE"
  round 80 hole 52: 1(-164,110) 2(164,-110)
  silkscreen extent -402,-118 402,118, body extent -378,-127 388,127, height 804
TO-220-F2 [mm] "CREE"
  rect 1.9x1.9 hole 1.4: 1(-2.54,0)
  round 1.9 hole 1.4: 2(2.54,0)
  silkscreen extent -5.25,-1.64 5.26,3.01, body extent -5.25,-1.64 5.26,3.01, height 19.09
TO-220AB [mil] "Copied from Altium's version of TO3B"
  rrect25% 76x118.11 hole 50: 1(-100,0)
  oval 76x118.11 hole 50: 2(0,0) 3(100,0)
  silkscreen extent -221,-59 221,126, body extent -221,-59 221,126, height 765
TO-262_100mil [mm]
  rect 2x2 hole 1.5: 1(0,0)
  round 2 hole 1.5: 2(2.54,-2.54) 3(5.08,0)
  silkscreen extent -2.79,-1.44 7.88,3.39, body extent -2.79,-2.91 7.88,3.39, height 16.13
VAR_S07K300E2 [mm] "EPCOS"
  round 1.4 hole 0.9: 1(-2.5,-1.05) 2(2.5,1.05)
  silkscreen extent -4.5,-2.3 4.5,2.3, body extent -4.46,-2.35 4.5,2.35, height 10.99
Vitec_75P8106 [mm] "Vitec"
  rect 1.62x1.62 hole 1.02: 1(-10.16,10.1)
  round 1.62 hole 1.02: 6(-10.16,-10.1) 7(10.16,-10.1) 14(10.16,10.1)
  silkscreen extent -12.95,-12.2 12.19,12.2, body extent -12.19,-12.2 12.19,12.2, height 19.05
WE-CMB_XL [mm] "Wurth"
  rect 2x2 hole 1.3: 1(-12.5,7.5)
  round 2 hole 1.3: 6(12.5,7.5) 7(12.5,-7.5) 12(-12.5,-7.5)
  silkscreen extent -15,-10.18 15,9.3, body extent -15.25,-10.5 15.25,10.5, height 35

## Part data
C1 C8: "CAP, CERM, 0.1uF, 50V, +/-10%, X7R, 0603"
C2 C3: "CAP, CERM, 10uF, 35V, +/-10%, X7R, 1206"
C4 C15: "CAP, AL, 100 µF, 25 V, +/- 20%, TH"
C5 C6 C7: "CAP, CERM, 470pF, 50V, +/-10%, X7R, 0603"
C9: "CAP, CERM, 0.1uF, 25V, +/-10%, X7R, 0603"
C10: "CAP, CERM, 1000pF, 50V, +/-10%, X7R, 0603"
C11 C12: "CAP, Film, 0.47uF, 275V, +/-20%, TH"
C13: "CAP, Film, 0.33uF, 275V, +/-20%, TH"
C14: "CAP, AL, 270 µF, 450 V, +/- 20%, 0.737 ohm, TH"
C17: "CAP, CERM, 47uF, 6.3V, +/-10%, X7R, 1210"
C18 C40 C42: "CAP, CERM, 0.1uF, 50V, +/-5%, X7R, 0805"
C19 C34: "CAP, CERM, 1uF, 50V, +/-10%, X7R, 0805"
C20: "CAP, CERM, 1000pF, 250V, +/-20%, E, Disc, 8x12mm"
C21 C27: library part ECW-H8123HA, "CAP FILM 0.016UF 630VDC RADIAL"
C22: "CAP, CERM, 1 µF, 50 V, +/- 10%, X7R, 0603"
C23: "CAP, Film, 0.012uF, 800V, +/-3%, TH"
C26: "CAP, CERM, 0.1 µF, 25 V, +/- 5%, C0G/NP0, 1206"
C28 C33: "CAP, AL, 330uF, 16V, +/-20%, 0.014 ohm, TH"
C29 C30 C31 C32: "CAP, AL, 1000uF, 16V, +/-20%, 0.03 ohm, TH"
C35: "CAP, CERM, 1 µF, 25 V, +/- 10%, X7R, 1206"
C36 C37: "CAP, CERM, 100pF, 50V, +/-1%, C0G/NP0, 0603"
C38: "CAP, CERM, 0.01 µF, 50 V, +/- 10%, X7R, 0603"
C39: library part GRM1885C1E102JA01D, "CAP, CERM, 1000pF, 25V, +/-5%, C0G/NP0, 0603"
C41: "CAP, CERM, 0.047uF, 50V, +/-10%, X7R, 0805"
C43 C45: "CAP, CERM, 10 µF, 50 V, +/- 10%, X5R, 1206_190"
C46: library part 06035A470JAT2A, "CAP, CERM, 47pF, 50V, +/-5%, C0G/NP0, 0603"
C47: "CAP, CERM, 0.1uF, 16V, +/-10%, X7R, 0603"
D1 D2: "Diode, Fast Rectifier, 800V, 0.2A, TVS, 1.7x.7x1.25mm"
D4 D5: "Diode, Ultrafast, 100V, 0.25A, SOD-323"
D6: "Diode, Switching-Bridge, 600V, 3A, TH"
D7: "Diode, Schottky, 600V, 4A, TH"
D8: "Diode, Switching-Bridge, 420V, 8A, TH"
D9 D13: library part BAS316,115, "Diode, Ultrafast, 100V, 0.25A, SOD-323"
D10: library part 1N4005-T, "DIODE GEN PURP 600V 1A DO41"
D11 D12: "Diode, Schottky, 45V, 20A, TH"
D17: "Diode, Zener, 12V, 300mW, SOD-323"
D18: "Diode, Zener, 18V, 500mW, SOD-123"
D19 D20: "Diode, Switching, 100V, 0.215A, SOT-23"
F1: "Fuse, 8A, 250V, TH"
H3 H4 H9 H10 H16 H21 H22: "HEX STANDOFF 6-32 NYLON 1-1/2\""
HS1 HS2 HS3: "HEATSINK VERT MAX CLIP, BLACK, 4.25 INCHES"
J1 J3 J6 J7 J8 J12 J13 J19 J21 J27: "Jumper Wire, 700mil spacing, Violet, pkg of 150, TH"
J2: "Header, 312mil, 3x1, Tin, TH"
J4: "Terminal Block, 4x1, 5.08mm, TH"
J5 J16 J20 J22: "Jumper Wire, 400 mil Spacing, Yellow, Pkg of 200"
J9 J10 J15 J17 J24: "Jumper Wire, 300mil spacing, Orange, pkg of 200"
J11 J14 J23 J25 J26: "Jumper Wire, 500mil spacing, Green, pkg of 200"
J18: "Jumper Wire, 600mil spacing, Blue, pkg of 150, TH"
L1: "Inductor, ?, , A, TH"
L2: "Coupled inductor, 2.2mH, 8A, 0.014 ohm, +/-30%, TH"
L3: "Inductor, Shielded, ?, 55uH, A, 0.065 ohm, TH"
Q1: "MOSFET, N-CH, 600V, 0.021A, SOT-23"
Q2 Q3 Q4: "MOSFET, N-CH, 650V, 25A, TO-262"
R1 R2 R3: "RES, 0 ohm, 5%, 0.25W, 1206"
R4 R5 R9 R16: "RES, 0, 5%, 0.25 W, 1206"
R6 R19: library part CMF503K0900FHEB, "RES 3.09M OHM 1/4W 1% AXIAL"
R7 R8 R17 R18: "RES, 3.09Meg ohm, 1%, 0.25W, 1206"
R10 R11 R12: "RES, 10.0Meg ohm, 1%, 0.25W, 1206"
R13: "RES, 75.0k ohm, 1%, 0.1W, 0603"
R14: "RES, 3.3Meg ohm, 5%, 0.1W, 0603"
R15 R23 R54: "RES, 100 k, 1%, 0.1 W, 0603"
R20 R21: "RES, 470 ohm, 1%, 0.1W, 0603"
R22: "RES, 2.21 k, 1%, 0.25 W, TH"
R24: "RES, 3.32k ohm, 1%, 0.1W, 0603"
R25: "RES, 10, 5%, 0.1 W, 0603"
R26: "RES, 3.3, 5%, 0.1 W, 0603"
R27: "RES, 1.00, 1%, 0.1 W, 0603"
R28 R37 R43 R49: "RES, 10.0k ohm, 1%, 0.1W, 0603"
R29 R33 R34: "RES, 1.20, 1%, 1 W, 2512"
R30 R31 R32: "RES, 0.1, 1%, 2 W, 2512"
R35 R42: "RES, 3.30 ohm, 1%, 0.25W, 1206"
R36: "RES, 2.2, 5%, 0.125 W, 0805"
R38: "RES, 1.00 ohm, 1%, 0.125W, 0805"
R39 R41: "RES, 51.1, 1%, 0.1 W, 0603"
R40: library part CRCW12061K00FKEA, "RES, 1.00k ohm, 1%, 0.25W, 1206"
R44: "RES, 1.20 k, 1%, 0.25 W, 1206"
R45: "RES, 100, 1%, 0.25 W, 1206"
R46: "RES, 5.10k ohm, 0.5%, 0.1W, 0805"
R47: "RES, 49.9 ohm, 1%, 0.25W, 1206"
R48: "RES, 10.0 M, 1%, 0.1 W, 0603"
R50: "RES, 18.0k ohm, 1%, 0.1W, 0603"
R51: library part CRCW060339K2FKEA, "RES, 39.2k ohm, 1%, 0.1W, 0603"
R52: library part RC0603FR-071K2L, "RES, 1.20k ohm, 1%, 0.1W, 0603"
R55: "RES, 1.10 M, 1%, 0.1 W, 0603"
R56: library part CRCW06030000Z0EA, "RES, 0 ohm, 5%, 0.1W, 0603"
R57: "RES, 0 ohm, 5%, 0.1W, 0603"
R58: "RES, 4.75 k, 1%, 0.1 W, 0603"
R59: "RES, 1.00 k, 1%, 0.25 W, 1206"
RT1 RT2: library part CL-40, "Thermistor NTC, 10 ohm, 25%, Disc, 220x770 mil"
S1 S2: "Switch, Toggle, SPST, 1Pos, TH"
T1: "LLC Transformer, 280uH, TH"
TP10 TP15: "Test Point, Multipurpose, Yellow, TH"
TP23: "Test Point, Multipurpose, Red, TH"
TP26: "Test Point, Multipurpose, Black, TH"
TP27 TP28: "Test Point, Multipurpose, White, TH"
U1: "CCM PFC and LLC Combo Controller, D0016A"
U2: "Single-Channel High-Speed Low-Side Gate Driver (with 4-A Peak Source and 8-A Peak Sink), DBV0006A"
U3: "High-Speed,4A, 600V High-side Low-side Gate Driver Device, D0014A"
U4: "Single Output LDO, 100 mA, Adjustable 1.2 to 18.5 V Output, 3 to 60 V Input, with Enable and Power Good, 8-pin MSOP (DGN), -40 to 125 degC, Green (RoHS & no Sb/Br)"
U5 U6: library part LTV-817, "Opto-Isolator, 1 Channel, TH"
U7: "Adjustable Precision Shunt Regulator, 34 ppm / degC, 100 mA, -40 to 85 degC, 3-pin SOT-23 (DBZ), Green (RoHS & no Sb/Br)"
V1: "Varistor, 300V, 1.75kA, 7MM Radial, TH"

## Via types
v1: diameter 19.68, hole 7.87, Top Layer to Bottom Layer, 4 vias

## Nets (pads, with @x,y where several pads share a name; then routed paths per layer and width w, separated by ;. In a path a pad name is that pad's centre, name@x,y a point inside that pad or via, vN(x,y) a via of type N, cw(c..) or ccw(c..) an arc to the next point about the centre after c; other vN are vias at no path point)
+VOUT: C28.1 C29.1 C30.1 C31.1 C32.1 C33.1 C34.1 D11.2 D12.2 J4.3 J4.4 R40.2 R45.2 R46.2 R47.2 TP23.1 TP27.1 | length 10499.3
  Bottom Layer w20: R45.2@5850,4257.09 R46.2@5850,4550 5890,4510 R47.2@5942.91,4510 5942.91,4427.09 6100,4270 6810,4270 7470,3610 8860,3610 9050,3420 9050,1360 9020,1330 J4.3@8950,1330
  Bottom Layer w75: D11.2@7510,2970 8060,2970 8448.43,2581.57 C29.1@8448.43,2420 C30.1@8448.43,2070 C31.1@8448.43,1720 C32.1@8448.43,1370 8448.43,820 C28.1@8498.43,770 C33.1@8498.43,340 ; 8458.43,1330 J4.3@8950,1330 J4.4@8950,1530 8950,1780 TP23.1@8960,1790
AC1: C11.1 D1.2 J2.1 L2.1 R17.2 TP10.1 V1.2 | length 4532
  Bottom Layer w20: J2.1@280,3498 938,3498 1030,3590 1030,4220 1480,4670 D1.2@1982.76,4670 1982.76,4792.76 2020,4830 R17.2@2872.91,4830
  Bottom Layer w100: L2.1@207.87,2615.28 167.09,2656.06 C11.1@167.09,2920 280,3032.91 J2.1@280,3498
AC2: C11.2 D2.2 F1.1 L2.6 R7.2 V1.1 | length 3760
  Bottom Layer w20: 844.72,3128.19 1230,3513.46 1230,4120 1670,4560 D2.2@1982.76,4560 1982.76,4487.24 2030,4440 2230,4440 2450,4660 R7.2@2612.91,4660
  Bottom Layer w100: 641.57,3128.19 F1.1@760,3128.19 844.72,3128.19 C11.2@1052.91,2920 1192.12,2780.79 L2.6@1192.12,2615.28
AGND: C3.1 C5.2 J15.2 J22.1 R13.2 R14.1 R23.1 U1.6 | length 501.5
  Bottom Layer w20: 3251.5,4008.5 3261.42,4008.5 C3.1@3312.91,4060 3285,4087.91 U1.6@3285,4152.72
  Bottom Layer w50: J22.1@2991.5,4008.5 R14.1@3050,4008.5 R23.1@3230,4008.5 3251.5,4008.5 J15.2@3290,3970
AGND1: C6.2 C7.2 C8.2 C9.2 J22.2 R24.2 | length 665.2
  Bottom Layer w25: J22.2@2980,4410 J22.2@2990,4410 3040,4410 3099.63,4469.63 3099.63,4470.87 3138.76,4510 3140,4510 3140,4550 3181.5,4591.5 C7.2@3190,4591.5 C6.2@3250,4591.5 C8.2@3310,4591.5 C9.2@3370,4591.5 R24.2@3430,4591.5 ; C8.2@3310.99,4588.39 R24.2@3426.89,4588.39
BULK: C14.1 C21.1 C23.1 D6.1 J1.2 J3.2 J18.2 L1.1 L1.3 Q3.2 | length 6026.4
  Bottom Layer w20: C14.1@3016.85,3130 3066.85,3180 J18.2@3480,3180
  Bottom Layer w75: 3790,2030 4803,2030 5070,2297 5070,2540 Q3.2@5040,2570
  Bottom Layer w100: C14.1@3016.85,3130 3116.85,3030 3120,3030 3120,2390 J1.2@3130,2380 3276.06,2233.94 C23.1@3460,2233.94 3540,2313.94 C21.1@3700,2313.94 3790,2223.94 3790,2030 3790,745.32 3515.15,470.47 3515.15,365.15 D6.1@3300,150
FB: J21.1 R59.2 U5.3 U6.3 | length 1906.2
  Bottom Layer w20: R59.2@3907.09,4450 3927.09,4470 J21.1@4090,4470 4350,4730 5190,4730 ; U6.3@5310,4470 5220,4470 5190,4500 5190,4730 ; U5.3@5310,4670 5250,4730 5190,4730
GD1: J10.1 J23.1 | length 70
  Bottom Layer w20: J10.1@4310,3950 J23.1@4310,4020
GD2: J5.2 J9.1 | length 462.1
  Bottom Layer w20: J5.2@3990,3880 4040,3930 4262.3,3930 4290.17,3902.13 4329.83,3902.13 4357.7,3930 4380,3930 J9.1@4400,3950
LLC_RCS: C17.1 C22.1 C23.2 C27.2 HS2.1 J27.2 Q4.3 R22.2 R29.1 R33.1 R34.1 R43.2 U3.5 | length 8093
  Bottom Layer w12: R22.2@3310,4700 3758.11,4700 3863.87,4594.24 3863.87,4410.67 3932.38,4342.16 3932.38,4262.16 3969.27,4225.27 3969.27,4009.27 3920,3960 3840,3960 3823.75,3943.75 3823.75,3555.64 3748.11,3480 3670,3480 3610,3420 3610,3379.92 R33.1@3590,3359.92 ; 3700,3380 3866.05,3380 4116.13,3630.08 4116.13,3718.17 4141.83,3743.87 4179.06,3743.87 4203.87,3719.06 4203.87,3673.87 4160,3630 4160,3590 4193.87,3556.13 4293.87,3556.13 4310,3540 4310,3391.89 4360,3341.89 4360,3260 4380,3240 U3.5@4407.28,3240 ; 4600,3220 4610,3220 4730,3340 4730,3400 4771.5,3441.5 R43.2@4860,3441.5
  Bottom Layer w20: 4445.67,3230 4455.67,3220 4600,3220
  Bottom Layer w25: R43.2@4860,3441.5 Q4.3@4928.5,3510
  Bottom Layer w50: C17.1@3050,3462.91 R34.1@3152.99,3359.92 ; 4621.34,3828.66 HS2.1@4621.34,4166.1
  Bottom Layer w75: R34.1@3211.57,3358.35 R33.1@3591.57,3358.35 ; C23.2@3460,2726.06 3506.06,2726.06 3560,2780 3560,3020 3700,3160 3700,3380 ; R33.1@3590,3359.92 3633.86,3359.92 C27.2@3700,3426.06 3846.06,3426.06 3920,3500 3920,3646.06 4093.94,3820 4630,3820 Q4.3@4940,3510 5270,3840 J27.2@5270,3910
MOSI: C10.2 R21.2 U1.13 | length 219.7
  Bottom Layer w20: U1.13@3385,4367.28 3385,4380.67 3445.91,4441.57 3480.08,4441.57 C10.2@3498.5,4460 R21.2@3498.5,4520
NetC4_1: C4.1 C18.1 C19.1 R4.2 U2.1 | length 1668.1
  Bottom Layer w20: U2.1@1684.13,3447.4 1665.94,3447.4 1646.57,3428.04 1646.57,3303.23 C19.1@1663.31,3286.5 1663.31,3190.96 C18.1@1662.34,3190 1662.34,3183.01 1609.34,3130 1560,3130 1520,3170 1520,3610 1952.91,4042.91 R4.2@1952.91,4180
NetC5_1: C5.1 R12.2 R13.1 R14.2 U1.8 | length 367.5
  Bottom Layer w20: C5.1@3170,4071.5 3185,4086.5 U1.8@3185,4152.72
  Bottom Layer w25: R12.2@2907.09,4030 2948.58,4071.5 R13.1@3110,4071.5 C5.1@3170,4071.5
NetC6_1: C6.1 R19.1 U1.10 | length 167.4
  Bottom Layer w20: U1.10@3235,4367.28 3235,4435 3250,4450 C6.1@3250,4528.5
NetC7_1: C7.1 R6.1 U1.9 | length 191
  Bottom Layer w25: R6.1@3150,4450 3185,4415 U1.9@3185,4367.28 ; R6.1@3150,4451.24 3190,4491.24 C7.1@3190,4528.5
NetC8_1: C8.1 R22.1 U1.11 | length 163.6
  Bottom Layer w20: U1.11@3285,4367.28 3285,4415 R22.1@3320,4450 ; R22.1@3310.99,4459.02 C8.1@3310.99,4525.39
NetC9_1: C9.1 J21.2 R24.1 U1.12 | length 236.3
  Bottom Layer w20: U1.12@3335,4367.28 3335,4376 3384.09,4425.09 3385.09,4425.09 J21.2@3385.09,4465.09 ; C9.1@3370,4528.5 R24.1@3430,4528.5 ; J21.2@3390,4470 3390,4527.2
NetC12_1: C12.1 L2.12 RT1.1 RT2.1 | length 1178.5
  Bottom Layer w100: L2.12@207.87,2024.72 207.87,1418.13 RT1.1@376,1250 376,930 RT2.1@366,920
